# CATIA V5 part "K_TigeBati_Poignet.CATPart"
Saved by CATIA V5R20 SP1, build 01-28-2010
Part number: tige_bati_poignet
Bounding box of the stored display mesh (mm): x 30 to 40, y -110 to 30, z -4.991 to 4.991
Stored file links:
  G:\Khaled_CFAO_2011\SIL\SIL_GR1\mroland\Khaled\CAD_CATIA_Modifie\K_TigeBati_Poignet.CATPart
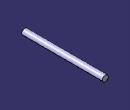
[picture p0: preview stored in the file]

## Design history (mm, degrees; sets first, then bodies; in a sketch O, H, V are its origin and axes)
Set1
  Sketch1 on xy-plane, origin (0, 0, 0), H (1, 0, 0), V (0, 1, 0)
    line L1 (30, 30) -> (30, -110)
    line L2 (30, -110) -> (35, -110)
    line L3 (35, -110) -> (35, 30)
    line L4 (30, 30) -> (35, 30)
    length L2 = 5 {= 5mm}
    length L3 = 140 {= 140mm}
    vertical: L1 V, L3 V
    horizontal: L2 H, L4 H
Body1 (main body)
  Shaft1: profile Sketch1, axis Sketch1.L3, angle 360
